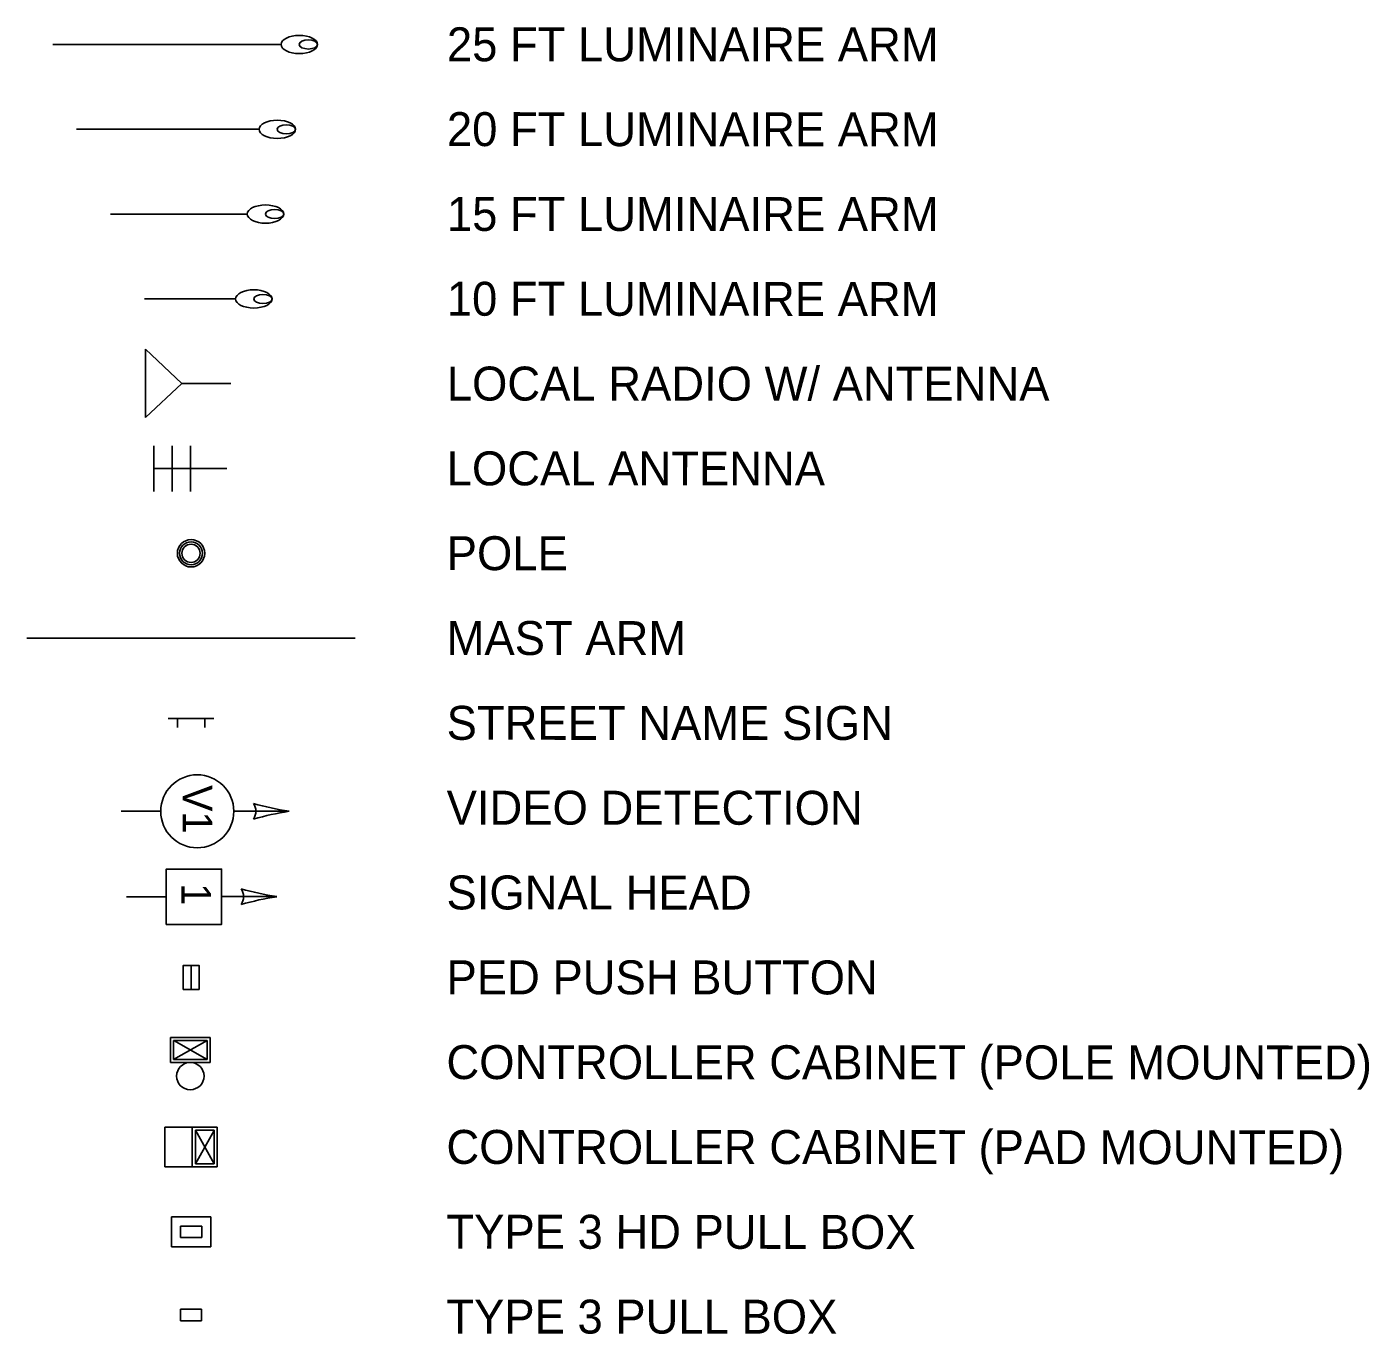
# Model space of a CAD drawing. Extents: x 994065 to 999017, y 1985203 to 1987174.
# Drawn here: x 995457.9 to 995605, y 1986200.2 to 1986343.6 of the extents above; entities that cross this region are included whole.
import ezdxf

# ---------------------------------------------------------------- set-up
doc = ezdxf.new("R2010")
doc.units = 0
for name, color, linetype in [('DSN_Drain_Alignment_ArDOT_BMCD_Rt', 7, 'Continuous'), ('DSN_DRAIN_Storm-Sewer_ArDOT_BMCD_Lt', 7, 'Continuous'), ('DSN_DRFT_Common-Annotations', 7, 'Continuous'), ('EX_CONTOUR_ANNOT_MAJOR', 7, 'Continuous'), ('EX_CONTOUR_ANNOT_MINOR', 7, 'Continuous'), ('EX_TERRAIN', 7, 'Continuous'), ('EX_TERRAIN_BOUNDARY', 7, 'Continuous'), ('S_ORTHO_IMAGE', 7, 'Continuous')]:
    doc.layers.add(name, color=color, linetype=linetype)

msp = doc.modelspace()

# ---------------------------------------------------------------- linework, layer by layer
at = {"layer": 'DSN_Drain_Alignment_ArDOT_BMCD_Rt'}
for p, q in [((995460.74, 1986341.64), (995485.74, 1986341.64)), ((995463.33, 1986332.34), (995483.33, 1986332.34)), ((995467.04, 1986323.04), (995482.04, 1986323.04)), ((995470.76, 1986313.74), (995480.76, 1986313.74)), ((995470.88, 1986300.73), (995470.88, 1986308.23)), ((995470.88, 1986308.23), (995474.88, 1986304.48)), ((995474.88, 1986304.48), (995470.88, 1986300.73)), ((995480.23, 1986304.48), (995474.88, 1986304.48)), ((995471.81, 1986297.64), (995471.81, 1986292.64)), ((995473.81, 1986297.64), (995473.81, 1986292.64)), ((995475.81, 1986297.64), (995475.81, 1986292.64)), ((995471.81, 1986295.14), (995479.81, 1986295.14)), ((995473.64, 1986230.03), (995473.64, 1986232.77)), ((995473.64, 1986232.77), (995477.97, 1986232.77)), ((995473.97, 1986232.44), (995477.64, 1986232.44)), ((995473.97, 1986230.36), (995473.97, 1986232.44)), ((995477.64, 1986232.44), (995473.97, 1986230.36)), ((995473.99, 1986232.44), (995477.64, 1986230.36)), ((995477.64, 1986230.36), (995477.64, 1986232.44)), ((995477.97, 1986230.03), (995477.97, 1986232.77)), ((995473.97, 1986230.36), (995477.64, 1986230.36)), ((995473.64, 1986230.03), (995477.97, 1986230.03))]:
    msp.add_line(p, q, dxfattribs=at)
msp.add_circle((995475.8, 1986228.53), 1.5, dxfattribs=at)
for centre, major_axis in [((995487.74, 1986341.64), (2, 0)), ((995488.74, 1986341.64), (-1, 0)), ((995485.33, 1986332.34), (2, 0)), ((995486.33, 1986332.34), (-1, 0)), ((995484.04, 1986323.04), (2, 0)), ((995485.04, 1986323.04), (-1, 0)), ((995482.76, 1986313.74), (2, 0)), ((995483.76, 1986313.74), (-1, 0))]:
    msp.add_ellipse(centre, major_axis=major_axis, ratio=0.5, dxfattribs=at)
at = {"layer": 'DSN_DRAIN_Storm-Sewer_ArDOT_BMCD_Lt'}
for p, q in [((995478.38, 1986267.75), (995473.38, 1986267.75)), ((995474.38, 1986266.75), (995474.38, 1986267.75)), ((995477.38, 1986267.75), (995477.38, 1986266.75)), ((995478.38, 1986267.75), (995477.38, 1986267.75))]:
    msp.add_line(p, q, dxfattribs=at)
at = {"layer": 'DSN_DRFT_Common-Annotations'}
msp.add_lwpolyline([(995475.02, 1986240.66), (995475.02, 1986238.03), (995475.89, 1986238.03), (995475.89, 1986240.66)], close=True, dxfattribs=at)
at = {"layer": 'EX_CONTOUR_ANNOT_MAJOR'}
for p, q in [((995478.05, 1986213.08), (995473.72, 1986213.08)), ((995473.72, 1986213.08), (995473.72, 1986209.81)), ((995478.05, 1986209.81), (995478.05, 1986213.08)), ((995474.72, 1986212.08), (995474.72, 1986210.81)), ((995477.05, 1986212.08), (995474.72, 1986212.08)), ((995477.05, 1986210.81), (995477.05, 1986212.08)), ((995473.72, 1986209.81), (995478.05, 1986209.81)), ((995474.72, 1986210.81), (995477.05, 1986210.81)), ((995474.71, 1986202.96), (995474.71, 1986201.69)), ((995477.04, 1986202.96), (995474.71, 1986202.96)), ((995477.04, 1986201.69), (995477.04, 1986202.96)), ((995474.71, 1986201.69), (995477.04, 1986201.69))]:
    msp.add_line(p, q, dxfattribs=at)
msp.add_lwpolyline([(995475.02, 1986238.03), (995476.76, 1986238.03), (995476.76, 1986240.66), (995475.02, 1986240.66)], close=True, dxfattribs=at)
at = {"layer": 'EX_CONTOUR_ANNOT_MINOR'}
for p, q in [((995468.23, 1986257.56), (995472.56, 1986257.56)), ((995480.56, 1986257.56), (995486.62, 1986257.56)), ((995468.81, 1986248.18), (995473.16, 1986248.18)), ((995479.22, 1986248.2), (995485.26, 1986248.2))]:
    msp.add_line(p, q, dxfattribs=at)
msp.add_lwpolyline([(995473.16, 1986245.16), (995473.16, 1986251.23), (995479.22, 1986251.23), (995479.22, 1986245.16)], close=True, dxfattribs=at)
msp.add_circle((995476.56, 1986257.56), 4, dxfattribs=at)
for centre, radius, start, end in [((995481.35, 1986257.56), 1.63, 328.1527, 31.8473), ((995491.03, 1986286.7), 29.47, 253.6536, 261.3917), ((995491.03, 1986228.42), 29.47, 98.6083, 106.3464), ((995480, 1986248.2), 1.63, 328.1527, 31.8473), ((995489.68, 1986277.34), 29.47, 253.6536, 261.3917), ((995489.68, 1986219.06), 29.47, 98.6083, 106.3464)]:
    msp.add_arc(centre, radius, start, end, dxfattribs=at)
at = {"layer": 'EX_TERRAIN'}
for p, q in [((995473.02, 1986222.91), (995478.76, 1986222.91)), ((995473.02, 1986222.91), (995473.02, 1986218.58)), ((995476.02, 1986222.91), (995476.02, 1986218.58)), ((995478.76, 1986222.91), (995478.76, 1986218.58)), ((995476.35, 1986222.58), (995476.35, 1986218.91)), ((995478.43, 1986218.91), (995476.35, 1986222.58)), ((995476.35, 1986222.58), (995478.43, 1986222.58)), ((995478.43, 1986222.56), (995476.35, 1986218.91)), ((995478.43, 1986222.58), (995478.43, 1986218.91)), ((995473.02, 1986218.58), (995478.76, 1986218.58)), ((995476.35, 1986218.91), (995478.43, 1986218.91))]:
    msp.add_line(p, q, dxfattribs=at)
at = {"layer": 'EX_TERRAIN_BOUNDARY'}
msp.add_line((995457.88, 1986276.55), (995493.88, 1986276.55), dxfattribs=at)
for radius in [1.5, 1.25, 1]:
    msp.add_circle((995475.88, 1986285.85), radius, dxfattribs=at)

# ---------------------------------------------------------------- texts
at = {"layer": 'EX_CONTOUR_ANNOT_MINOR'}
for s, p in [('V1', (995474.96, 1986260.44)), ('1', (995474.81, 1986249.66))]:
    msp.add_text(s, height=3.25, rotation=270, dxfattribs=at).set_placement(p)
at = {"layer": 'S_ORTHO_IMAGE'}
for s, p in [('25 FT LUMINAIRE ARM', (995503.92, 1986339.8)), ('20 FT LUMINAIRE ARM', (995503.92, 1986330.5)), ('15 FT LUMINAIRE ARM', (995503.92, 1986321.2)), ('10 FT LUMINAIRE ARM', (995503.91, 1986311.9)), ('LOCAL RADIO W/ ANTENNA', (995503.91, 1986302.6)), ('LOCAL ANTENNA', (995503.9, 1986293.3)), ('POLE', (995503.9, 1986284)), ('MAST ARM', (995503.89, 1986274.7)), ('STREET NAME SIGN', (995503.89, 1986265.4)), ('VIDEO DETECTION', (995503.89, 1986256.1)), ('SIGNAL HEAD', (995503.88, 1986246.8)), ('PED PUSH BUTTON', (995503.88, 1986237.5)), ('CONTROLLER CABINET (POLE MOUNTED)', (995503.87, 1986228.2)), ('CONTROLLER CABINET (PAD MOUNTED)', (995503.87, 1986218.9)), ('TYPE 3 HD PULL BOX', (995503.87, 1986209.6)), ('TYPE 3 PULL BOX', (995503.86, 1986200.3))]:
    msp.add_text(s, height=3.72, rotation=359.9748, dxfattribs=at).set_placement(p)

doc.saveas('drawing.dxf')
